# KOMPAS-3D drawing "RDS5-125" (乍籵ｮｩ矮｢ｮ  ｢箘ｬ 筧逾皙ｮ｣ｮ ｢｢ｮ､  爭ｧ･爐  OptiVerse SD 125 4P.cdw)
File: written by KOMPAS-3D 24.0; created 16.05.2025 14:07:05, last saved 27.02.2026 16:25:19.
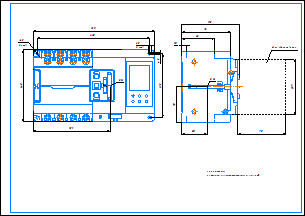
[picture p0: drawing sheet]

Document properties: Утвердил: Строгонов; Автор: keaz-admin; Проверил: Дорошев; Форматы листов документа: A2; Полное имя файла: D:\Проекты\OptiVerse SD\OptiVerse SD\OptiVerse SD 125 4P\КД\ГЖИК.648446.003 ГЧ OptiVerse SD 125 4P (без рамки).cdw; Масса: 4.5; Т. контр.: Пашков А.Е.; Наименование: Устройство автоматического ввода резерва OptiVerse SD 125 4P / Габаритный чертеж; Н. контр.: Гаврикова; Количество листов документа: 1; Разработал: Сулейманова

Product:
- Body: Тело 4
    Масса: 0.000009
- Body: Тело 3
    Масса: 0.000001
- Component [assembly]: RDS5-125.STEP  | qty 1  | Масса: 17.512013; source file: ..\3D\RDS5-125.STEP.a3d
- Body: Тело 2
    Масса: 0.000069
- Part/product: RDS5-125
    Масса: 17.512124
    Форматы листов документа: A2

Views: Проекционный вид 2, Вид 1
Referenced files in D:\Проекты\OptiVerse SD\OptiVerse SD\RDS5-125A\КД\: ГЖИК.648446.003 СБ OptiVerse SD 125 4P.cdw
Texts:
  Зона обслуживания
  Устройство автоматического
  ввода резерва OptiVerse SD 125 4P
  Габаритный чертеж
  ГЖИК.648446.003ГЧ
  Сулейманова
  Дорошев
  ГЖИК.648446.003
  АО "КЭАЗ"
  Гаврикова
  Строгонов
  Пашков А.Е.
  Без основной надписи.
Dimensions and other numbers on the sheet: 115; 96; 10; 65; 90; 109; 70; 50; 1:1; 0; 1; 2; 4,5

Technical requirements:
  Ц.М. - центр масс.
  Отклонение координат от центра масс не более 10 %.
